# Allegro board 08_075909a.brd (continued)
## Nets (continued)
Pads without a net: MINIQ2 1 2 3 4 5 8; SHDNL_SEL 3; SW1 8 9; U2 6 9; U3 1 2; U4 3 4 5 6 9 10 11 12; U5 2

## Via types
v1: diameter 0.508, hole 0.254, TOP to BOTTOM, 507 vias

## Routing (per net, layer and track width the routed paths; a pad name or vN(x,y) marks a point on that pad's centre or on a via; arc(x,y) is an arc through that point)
3.3V: length 34.9
  TOP w0.381: U2.1 117.93,57.03 117.93,59.16 ; MINIQ1.15 124.71,45.85 124.71,55.75 123.95,56.52 R132.1 117.93,59.16 ; 117.93,59.16 117.22,59.87 117.22,66.29 117.94,67.01 U4.1
5.0V: length 101.4
  TOP w0.635: R34.2 119.85,99.03 v1(120.78,99.03)
  BOTTOM w0.762: J8.1 96.27,167.89 102.34,161.82 123.42,161.82 125.86,159.38 125.86,114.43 120.78,109.35 v1(120.78,99.03) 120.75,99.03 119.17,97.45 R24.2
GND_POWER: length 695.9
  TOP w0.203: v1(66.93,113.28) 67.14,113.07 67.53,113.07 U1.14 ; v1(19.71,160.66) 19.71,161.66 C104.2 ; D3.2 22,160.78 v1(20.7,160.78) ; 58.75,118.54 58.75,118.61 ; U1.6 70.1,109.99 v1(70.1,109.74) ; v1(69.44,110.49) 69.44,110.74 70.33,111.64 U1.8 ; D34.3 v1(20.57,144.27) ; v1(71.12,108.71) 71.65,108.71 71.88,108.94 U1.2 ; D29.3 v1(105.41,145.8)
  TOP w0.254: v1(61.98,109.22) 61.98,109.54 61.7,109.81 61.7,109.83 U1.28
  TOP w0.381: C81.2 v1(77.85,135.64) ; Q1.6 68.88,133.01 v1(69.22,133.35) ; v1(64.52,134.75) 64.99,134.75 Q1.3 ; U4.7 v1(121.84,68.24) ; C77.2 v1(79.76,134.11) ; U2.7 121.84,55.45 v1(122.17,55.12) ; 50,135.05 v1(48.9,136.15)
  TOP w0.508: v1(60.33,164.21) 60.31,164.22 GPIO_AUX2.2 ; J7.1 57.5,10.57 57.91,10.16 v1(60.2,10.16) ; v1(53.34,113.79) C14.2 ; C105.2 53.59,163.18 v1(53.59,162.18) ; C9.2 58.75,118.54 ; 71.34,116.83 71.32,116.83 C78.2 ; 71.34,116.83 71.81,117.3 v1(71.81,117.7) ; 71.34,116.83 71.07,116.56 70.97,116.56 ; C108.2 63.78,163.28 63.78,162.71 63.75,162.69 v1(63.75,162.31) ; 13.86,150.01 C102.1 14.06,150.01 ; J5.23 J5.24 ; v1(80.9,164.08) 80.89,164.1 GPIO_AUX0.2 ; v1(56.25,116.97) C11.2 ; v1(31.18,148.59) D28.A ; v1(41.03,165.97) 40.33,165.97 GPIO_AUX4.2 ; R152.2 v1(30.35,151.13) ; R155.2 v1(104.39,142.75) ; v1(75.44,10.16) 73.41,10.16 72.03,8.78 J7.GND1 ; v1(39.5,162.22) 39.5,161.77 D4.2 ; 14.06,138.65 C101.2 13.86,138.65 ; GPIO_AUX1.2 70.52,164.25 v1(70.48,164.21) ; R161.2 v1(104.39,148.84) ; R10.1 98.01,116.87 v1(97.65,117.24) ; C10.2 v1(57.27,117.99) ; J7.GND2 54.97,9.8 54.61,10.16 v1(52.32,10.16) ; GPIO_AUX3.2 50.13,164.25 v1(50.16,164.21) ; 58.75,118.61 v1(58.32,119.04) ; D7.2 v1(59.18,158.24) ; C109.2 41.77,163.58 v1(42.8,163.58) ; v1(73.91,162.18) 73.91,163.28 C107.2 ; v1(54.1,114.88) 54.28,114.88 C13.2 55.1,114.07 ; C12.2 55.31,115.89 v1(55.12,115.89) ; D6.2 v1(69.34,158.24) ; 27.3,161.74 R31.2 ; v1(61.72,122.17) C83.2 ; C106.2 84.35,163.21 v1(84.35,161.67) ; R150.2 v1(30.35,137.41) ; GPIO_AUX5.2 20.01,165.97 v1(20.71,165.97) ; 44.61,136.85 43.55,137.91 43.55,137.93 v1(43.05,138.43) ; D5.2 v1(79.76,158.24) ; 60.18,119.15 C8.2 59.31,120.02 v1(59.26,120.02) ; v1(31.18,139.95) D31.A ; D32.3 25.83,127.25 v1(24.39,127.25) ; C80.2 v1(60.45,120.9) ; D33.3 v1(111,127.76) ; D8.2 v1(49.02,158.24) ; R168.2 v1(18.03,123.19) ; R169.2 v1(18.29,131.57)
  TOP w0.635: ALARM_OUT_LP.GND1 4.22,104.89 ; 4.22,104.89 v1(5.83,104.89) ; 4.22,104.89 ALARM_OUT_LP.GND2 ; GPIO_AUX0.GND1 77.18,171.02 v1(80.01,171.02) 83.09,171.02 GPIO_AUX0.GND2 ; v1(77.47,102.87) 78.86,101.48 78.86,101.46 C18.2 v1(80.26,100.08) ; GPIO_AUX5.GND2 21.88,171.07 v1(19.05,171.07) 15.97,171.07 GPIO_AUX5.GND1 ; RXLP_CONN.GND2 v1(2.8,132.59) ; C21.2 91.98,94.1 v1(92.91,93.17) ; v1(76.68,113.28) 75.74,112.34 C3.2 ; TXLP_CONN.GND1 v1(2.8,139.19) ; v1(123.8,104.9) 123.8,102.66 ALARM_IN_UP.GND2 ; TXUP_CONN.GND1 123.82,131.64 v1(123.82,133.22) ; v1(94.61,121.28) R134.2 ; v1(88.14,160.02) C17.2 88.14,161.43 ; 90.4,162.8 C16.2 ; 90.4,162.8 90.4,164.78 R139.2 ; 90.4,162.8 v1(90.4,161.57) ; C82.2 69.36,118.16 v1(69.19,118.16) ; GPIO_AUX3.GND1 46.42,171.04 v1(49.53,171.04) 52.33,171.04 GPIO_AUX3.GND2 ; v1(108.08,109.19) 107.21,109.19 C87.2 ; R110.2 108.05,114.96 v1(108.2,114.81) ; v1(27.3,160.15) 27.3,161.74 ; v1(9.14,97.79) C93.2 10.64,97.79 10.64,99.09 10.41,99.31 D9.A ; RXLP_CONN.GND1 v1(2.8,122.43) ; C5.2 v1(73.38,116.05) ; GPIO_AUX2.GND1 56.61,171.07 v1(59.44,171.07) 62.52,171.07 GPIO_AUX2.GND2 ; U5.4 102.06,106.91 102.97,107.82 v1(104.27,107.82) ; R112.2 11.17,110.02 D10.A 10.22,109.97 v1(9.41,109.97) ; v1(93.66,123.7) D30.A ; R30.1 v1(40.89,123.7) ; C4.2 v1(75.18,114.3) ; 14.06,138.65 v1(15.01,138.65) ; GPIO_AUX1.GND2 72.73,171.07 v1(70.1,171.07) 66.82,171.07 GPIO_AUX1.GND1 ; C15.2 v1(77.98,112.01) ; RXUP_CONN.GND1 124.59,149.54 v1(124.59,150.88) ; TXUP_CONN.GND2 123.82,124.14 v1(123.82,122.94) ; v1(93.66,132.08) D26.A ; v1(123.8,106.05) 123.8,108.57 ALARM_IN_UP.GND1 ; R147.2 95.62,134.54 v1(94.23,134.54) ; CURRENTSENSE.GND2 32.17,171.19 v1(29.21,171.19) 26.25,171.19 CURRENTSENSE.GND1 ; GPIO_AUX4.GND2 42.2,171.07 v1(39.37,171.07) 36.29,171.07 GPIO_AUX4.GND1 ; v1(124.59,140.91) 124.59,142.05 RXUP_CONN.GND2 ; C100.2 v1(114.71,13.26) ; 14.06,150.01 v1(15.06,150.01) ; TXLP_CONN.GND2 v1(2.8,149.61)
  L2_GND w0.381: v1(69.22,133.35) 69.34,133.35 ; v1(69.22,133.35) 69.09,133.35 ; v1(69.22,133.35) 69.22,133.48 ; v1(69.22,133.35) 69.22,133.22 ; 91.82,140.21 v1(91.95,140.21) ; v1(91.95,140.21) 92.08,140.21 ; v1(91.95,140.21) 91.95,140.34 ; v1(91.95,140.21) 91.95,140.08 ; v1(108.08,109.19) 108.2,109.19 ; v1(108.08,109.19) 108.08,109.07 ; v1(108.08,109.19) 107.95,109.19 ; v1(108.08,109.19) 108.08,109.32 ; v1(70.1,109.74) 70.23,109.74 ; v1(70.1,109.74) 70.1,109.87 ; v1(70.1,109.74) 69.98,109.74 ; v1(70.1,109.74) 70.1,109.61 ; 94.61,121.16 v1(94.61,121.28) ; v1(94.61,121.28) 94.74,121.28 ; v1(94.61,121.28) 94.49,121.28 ; v1(94.61,121.28) 94.61,121.41 ; 79.63,134.11 v1(79.76,134.11) ; v1(79.76,134.11) 79.88,134.11 ; v1(79.76,134.11) 79.76,133.98 ; v1(79.76,134.11) 79.76,134.24 ; 69.31,110.49 v1(69.44,110.49) ; v1(69.44,110.49) 69.44,110.62 ; v1(69.44,110.49) 69.57,110.49 ; v1(69.44,110.49) 69.44,110.36 ; 77.98,111.89 v1(77.98,112.01) ; v1(77.98,112.01) 77.85,112.01 ; v1(77.98,112.01) 77.98,112.14 ; v1(77.98,112.01) 78.11,112.01 ; v1(76.25,111.53) 76.38,111.53 ; v1(76.25,111.53) 76.12,111.53 ; v1(76.25,111.53) 76.25,111.66 ; v1(76.25,111.53) 76.25,111.4 ; 93.18,113.22 J1.2 ; J1.2 94.89,113.22 ; J1.2 93.18,111.51 ; J1.2 94.89,111.51 ; J1.8 84.12,122.28 ; J1.8 82.41,123.99 ; J1.8 82.41,122.28 ; J1.8 84.12,123.99 ; J5.23 33.53,152.34 ; J5.23 32.32,151.13 ; J5.23 33.53,149.92 ; J5.23 34.74,151.13 ; 91.95,102.53 v1(91.95,102.66) ; v1(91.95,102.66) 92.08,102.66 ; v1(91.95,102.66) 91.82,102.66 ; v1(91.95,102.66) 91.95,102.78 ; v1(71.81,117.7) 71.93,117.7 ; v1(71.81,117.7) 71.81,117.58 ; v1(71.81,117.7) 71.68,117.7 ; v1(71.81,117.7) 71.81,117.83 ; v1(111,127.76) 111,127.89 ; v1(111,127.76) 111,127.63 ; v1(111,127.76) 111.13,127.76 ; v1(111,127.76) 110.87,127.76 ; 45.02,148.59 J5.14 ; J5.14 47.44,148.59 ; J5.14 46.23,147.38 ; J5.14 46.23,149.8 ; 84.84,106.93 v1(84.96,106.93) ; v1(84.96,106.93) 84.96,106.81 ; v1(84.96,106.93) 84.96,107.06 ; v1(84.96,106.93) 85.09,106.93 ; 104.14,107.82 v1(104.27,107.82) ; v1(104.27,107.82) 104.27,107.95 ; v1(104.27,107.82) 104.27,107.7 ; v1(104.27,107.82) 104.39,107.82 ; 76.56,113.28 v1(76.68,113.28) ; v1(76.68,113.28) 76.81,113.28 ; v1(76.68,113.28) 76.68,113.41 ; v1(76.68,113.28) 76.68,113.16 ; 38.61,149.92 J5.19 ; J5.19 38.61,152.34 ; J5.19 39.82,151.13 ; J5.19 37.4,151.13 ; J5.8 53.85,149.8 ; J5.8 55.06,148.59 ; J5.8 52.64,148.59 ; J5.8 53.85,147.38 ; 75.06,114.3 v1(75.18,114.3) ; v1(75.18,114.3) 75.18,114.43 ; v1(75.18,114.3) 75.18,114.17 ; v1(75.18,114.3) 75.31,114.3 ; J5.1 61.47,152.34 ; J5.1 61.47,149.92 ; J5.1 62.68,151.13 ; J5.1 60.26,151.13 ; 104.65,133.73 v1(104.65,133.86) ; v1(104.65,133.86) 104.78,133.86 ; v1(104.65,133.86) 104.65,133.99 ; v1(104.65,133.86) 104.52,133.86 ; 94.11,134.54 v1(94.23,134.54) ; v1(94.23,134.54) 94.36,134.54 ; v1(94.23,134.54) 94.23,134.67 ; v1(94.23,134.54) 94.23,134.41 ; 88.67,129.46 v1(88.8,129.46) ; v1(88.8,129.46) 88.93,129.46 ; v1(88.8,129.46) 88.8,129.59 ; v1(88.8,129.46) 88.8,129.34 ; 5.08,20.95 B0P-.1 ; B0P-.1 5.08,23.24 ; B0P-.1 6.22,22.1 ; B0P-.1 3.94,22.1 ; v1(111.76,120.9) 111.89,120.9 ; v1(111.76,120.9) 111.76,121.03 ; v1(111.76,120.9) 111.76,120.78 ; v1(111.76,120.9) 111.63,120.9 ; v1(100.58,96.77) 100.58,96.9 ; v1(100.58,96.77) 100.46,96.77 ; v1(100.58,96.77) 100.71,96.77 ; v1(100.58,96.77) 100.58,96.65 ; v1(73.38,116.05) 73.38,116.18 ; v1(73.38,116.05) 73.38,115.93 ; v1(73.38,116.05) 73.51,116.05 ; v1(73.38,116.05) 73.25,116.05 ; v1(97.65,117.24) 97.77,117.24 ; v1(97.65,117.24) 97.65,117.11 ; v1(97.65,117.24) 97.52,117.24 ; v1(97.65,117.24) 97.65,117.37 ; v1(71.12,108.71) 71.12,108.84 ; v1(71.12,108.71) 71.12,108.58 ; v1(71.12,108.71) 70.99,108.71 ; v1(71.12,108.71) 71.25,108.71 ; 77.47,102.74 v1(77.47,102.87) ; v1(77.47,102.87) 77.6,102.87 ; v1(77.47,102.87) 77.47,103 ; v1(77.47,102.87) 77.34,102.87 ; 93.53,132.08 v1(93.66,132.08) ; v1(93.66,132.08) 93.66,131.95 ; v1(93.66,132.08) 93.66,132.21 ; v1(93.66,132.08) 93.79,132.08 ; J1.6 87.71,120.4 ; J1.6 87.71,118.69 ; J1.6 86,118.69 ; J1.6 86,120.4 ; 64.52,134.62 v1(64.52,134.75) ; v1(64.52,134.75) 64.39,134.75 ; v1(64.52,134.75) 64.52,134.87 ; v1(64.52,134.75) 64.64,134.75 ; 38.61,147.38 J5.20 ; J5.20 37.4,148.59 ; J5.20 39.82,148.59 ; J5.20 38.61,149.8 ; J5.13 47.44,151.13 ; J5.13 46.23,152.34 ; J5.13 46.23,149.92 ; J5.13 45.02,151.13 ; v1(66.93,113.28) 67.06,113.28 ; v1(66.93,113.28) 66.93,113.41 ; v1(66.93,113.28) 66.8,113.28 ; v1(66.93,113.28) 66.93,113.16 ; v1(78.36,125.09) 78.36,125.22 ; v1(78.36,125.09) 78.23,125.09 ; v1(78.36,125.09) 78.49,125.09 ; v1(78.36,125.09) 78.36,124.97 ; v1(77.85,135.64) 77.85,135.76 ; v1(77.85,135.64) 77.98,135.64 ; v1(77.85,135.64) 77.85,135.51 ; v1(77.85,135.64) 77.72,135.64 ; 91.95,126.92 v1(91.95,127.05) ; v1(91.95,127.05) 91.82,127.05 ; v1(91.95,127.05) 91.95,127.18 ; v1(91.95,127.05) 92.08,127.05 ; J1.14 73.34,133.06 ; J1.14 71.63,133.06 ; J1.14 73.34,134.77 ; J1.14 71.63,134.77 ; J5.24 33.53,149.8 ; J5.24 34.74,148.59 ; J5.24 33.53,147.38 ; J5.24 32.32,148.59 ; 92.91,93.04 v1(92.91,93.17) ; v1(92.91,93.17) 93.04,93.17 ; v1(92.91,93.17) 92.79,93.17 ; v1(92.91,93.17) 92.91,93.29 ; 105.66,43.37 MINIQ1.1 ; MINIQ1.1 105.66,45.78 ; MINIQ1.1 104.46,44.58 ; MINIQ1.1 106.87,44.58 ; v1(64.52,109.22) 64.52,109.35 ; v1(64.52,109.22) 64.52,109.09 ; v1(64.52,109.22) 64.39,109.22 ; v1(64.52,109.22) 64.64,109.22 ; 79.25,120.65 v1(79.38,120.65) ; v1(79.38,120.65) 79.5,120.65 ; v1(79.38,120.65) 79.38,120.78 ; v1(79.38,120.65) 79.38,120.52 ; v1(69.19,118.16) 69.19,118.29 ; v1(69.19,118.16) 69.06,118.16 ; v1(69.19,118.16) 69.19,118.03 ; v1(69.19,118.16) 69.32,118.16 ; 108.2,114.68 v1(108.2,114.81) ; v1(108.2,114.81) 108.33,114.81 ; v1(108.2,114.81) 108.2,114.94 ; v1(108.2,114.81) 108.08,114.81 ; v1(111.51,137.41) 111.63,137.41 ; v1(111.51,137.41) 111.51,137.54 ; v1(111.51,137.41) 111.51,137.29 ; v1(111.51,137.41) 111.38,137.41 ; J2.12 44.06,116.88 ; J2.12 44.06,118.59 ; J2.12 42.36,116.88 ; J2.12 42.36,118.59 ; 91.19,168.72 J8.3 ; J8.3 92.39,169.93 ; J8.3 91.19,171.13 ; J8.3 89.98,169.93 ; 93.53,123.7 v1(93.66,123.7) ; v1(93.66,123.7) 93.66,123.83 ; v1(93.66,123.7) 93.79,123.7 ; v1(93.66,123.7) 93.66,123.57 ; 52.64,151.13 J5.7 ; J5.7 53.85,152.34 ; J5.7 53.85,149.92 ; J5.7 55.06,151.13 ; v1(80.26,100.08) 80.39,100.08 ; v1(80.26,100.08) 80.26,100.2 ; v1(80.26,100.08) 80.26,99.95 ; v1(80.26,100.08) 80.14,100.08 ; MINIQ2.6 119.5,94.89 ; MINIQ2.6 118.29,93.69 ; MINIQ2.6 117.08,94.89 ; MINIQ2.6 118.29,96.1 ; 60.26,148.59 J5.2 ; J5.2 61.47,149.8 ; J5.2 62.68,148.59 ; J5.2 61.47,147.38 ; 65.99,107.62 v1(66.12,107.62) ; v1(66.12,107.62) 66.24,107.62 ; v1(66.12,107.62) 66.12,107.49 ; v1(66.12,107.62) 66.12,107.75 ; v1(66.55,102.11) 66.68,102.11 ; v1(66.55,102.11) 66.42,102.11 ; v1(66.55,102.11) 66.55,101.98 ; v1(66.55,102.11) 66.55,102.24
  L3_GND w0.381: 91.19,168.72 J8.3 ; J8.3 92.39,169.93 ; J8.3 91.19,171.13 ; J8.3 89.98,169.93 ; 32.32,151.13 J5.23 ; J5.23 33.53,149.92 ; J5.23 34.74,151.13 ; J5.23 33.53,152.34 ; J1.6 87.71,120.4 ; J1.6 86,120.4 ; J1.6 86,118.69 ; J1.6 87.71,118.69 ; J5.1 62.68,151.13 ; J5.1 61.47,152.34 ; J5.1 61.47,149.92 ; J5.1 60.26,151.13 ; 33.53,147.38 J5.24 ; J5.24 34.74,148.59 ; J5.24 33.53,149.8 ; J5.24 32.32,148.59 ; J1.2 94.89,113.22 ; J1.2 94.89,111.51 ; J1.2 93.18,111.51 ; J1.2 93.18,113.22 ; 45.02,148.59 J5.14 ; J5.14 46.23,147.38 ; J5.14 46.23,149.8 ; J5.14 47.44,148.59 ; J5.20 39.82,148.59 ; J5.20 38.61,147.38 ; J5.20 38.61,149.8 ; J5.20 37.4,148.59 ; 46.23,149.92 J5.13 ; J5.13 47.44,151.13 ; J5.13 46.23,152.34 ; J5.13 45.02,151.13 ; 117.08,94.89 MINIQ2.6 ; MINIQ2.6 119.5,94.89 ; MINIQ2.6 118.29,96.1 ; MINIQ2.6 118.29,93.69 ; MINIQ1.1 105.66,45.78 ; MINIQ1.1 105.66,43.37 ; MINIQ1.1 106.87,44.58 ; MINIQ1.1 104.46,44.58 ; 82.41,123.99 J1.8 ; J1.8 84.12,122.28 ; J1.8 82.41,122.28 ; J1.8 84.12,123.99 ; J1.14 73.34,133.06 ; J1.14 73.34,134.77 ; J1.14 71.63,134.77 ; J1.14 71.63,133.06 ; J5.2 62.68,148.59 ; J5.2 61.47,147.38 ; J5.2 60.26,148.59 ; J5.2 61.47,149.8 ; 52.64,148.59 J5.8 ; J5.8 55.06,148.59 ; J5.8 53.85,149.8 ; J5.8 53.85,147.38 ; J5.7 55.06,151.13 ; J5.7 53.85,152.34 ; J5.7 53.85,149.92 ; J5.7 52.64,151.13 ; B0P-.1 5.08,23.24 ; B0P-.1 6.22,22.1 ; B0P-.1 5.08,20.95 ; B0P-.1 3.94,22.1 ; J5.19 39.82,151.13 ; J5.19 38.61,152.34 ; J5.19 37.4,151.13 ; J5.19 38.61,149.92 ; 42.36,116.88 J2.12 ; J2.12 44.06,116.88 ; J2.12 44.06,118.59 ; J2.12 42.36,118.59
  L3_GND w0.635: PACK-.1 2.55,12.9 ; PACK-.1 5.07,12.9 ; PACK-.1 2.55,18.59 ; PACK-.1 5.07,18.59 ; B0P-.1 3.92,20.94 ; B0P-.1 3.92,23.25 ; B0P-.1 6.24,20.94 ; B0P-.1 6.24,23.25
  BOTTOM w0.254: 75.11,110.92 C2.2
  BOTTOM w0.305: v1(105.66,42.8) MINIQ1.1 ; D25.2 v1(98.17,46.1)
  BOTTOM w0.381: 74.57,111.38 74.95,111 C2.2 75.26,110.77 75.67,110.36 ; 46.76,8.81 46.76,8.82 C43.1 46.76,11.45 46.76,11.46 ; 45.02,151.13 J5.13 ; J5.13 47.44,151.13 ; J5.13 46.23,152.34 ; 115.82,52.45 D21.2 v1(115.82,51.31) ; 37.4,148.59 J5.20 38.61,147.38 ; 91.95,102.53 v1(91.95,102.66) ; v1(91.95,102.66) 92.08,102.66 ; v1(91.95,102.66) 91.82,102.66 ; v1(91.95,102.66) 91.95,102.78 ; v1(110.74,51.31) D23.2 110.74,52.45 ; 72.13,114.79 72.41,114.5 C76.2 72.62,114.2 73,113.82 ; J2.12 44.06,118.59 ; J2.12 44.06,116.88 ; J2.12 42.36,116.88 ; J2.12 42.36,118.59 ; 120.9,52.45 D19.2 v1(120.9,51.31) ; 54.38,8.81 54.38,8.82 C42.1 54.38,11.45 54.38,11.46 ; J1.6 87.71,120.4 ; J1.6 86,118.69 ; J1.6 86,120.4 ; J1.6 87.71,118.69 ; MINIQ2.6 119.5,94.89 ; MINIQ2.6 118.29,96.1 ; MINIQ2.6 118.29,93.69 ; 31.52,11.46 31.52,11.45 C45.1 31.52,8.82 31.52,8.81 ; J5.2 62.68,148.59 ; J5.2 60.26,148.59 ; J5.2 61.47,147.38 ; 45.02,148.59 J5.14 46.23,147.38 ; 62,11.46 62,11.45 C41.1 62,8.82 62,8.81 ; 84.96,106.81 v1(84.96,106.93) ; v1(84.96,106.93) 84.96,107.06 ; v1(84.96,106.93) 85.09,106.93 ; v1(84.96,106.93) 84.84,106.93 ; 23.9,8.81 23.9,8.82 C46.1 23.9,11.45 23.9,11.46 ; B0P-.1 6.22,22.1 ; B0P-.1 5.08,23.24 ; B0P-.1 3.94,22.1 ; B0P-.1 5.08,20.95 ; Q2.6 78.1,124.83 v1(78.36,125.09) ; 108.2,52.45 D24.2 v1(108.2,51.31) ; 32.32,151.13 J5.23 ; J5.23 34.74,151.13 ; J5.23 33.53,152.34 ; J5.23 33.53,149.92 ; J5.19 39.82,151.13 ; J5.19 38.61,152.34 ; J5.19 37.4,151.13 ; 71.63,134.77 J1.14 ; J1.14 71.63,133.06 ; J1.14 73.34,134.77 ; 32.23,115.95 31.6,115.32 C84.2 31.16,114.96 30.45,114.25 ; 84.86,11.46 84.86,11.45 C38.1 84.86,8.82 84.86,8.81 ; 35.41,116.56 34.74,115.89 C85.2 34.73,115.83 34.16,115.27 ; R12.1 89.65,128.69 90.35,127.99 ; R12.1 89.54,128.69 88.95,128.09 ; R12.1 89.57,128.69 v1(88.8,129.46) ; 39.14,8.81 39.14,8.82 C44.1 39.14,11.45 39.14,11.46 ; v1(113.28,51.31) D22.2 113.28,52.45 ; J5.24 33.53,149.8 ; J5.24 34.74,148.59 ; J5.24 33.53,147.38 ; J5.24 32.32,148.59 ; J5.7 55.06,151.13 ; J5.7 52.64,151.13 ; J5.7 53.85,152.34 ; 65.6,110.46 65.12,109.98 R28.2 65.14,109.89 65.74,109.3 ; 107.72,8.81 107.72,8.82 C35.1 107.72,11.45 107.72,11.46 ; C19.2 87.1,105.08 ; C19.2 84.66,102.64 ; C19.2 85.05,104.68 ; 115.34,11.46 115.34,11.45 C34.1 115.34,8.82 115.34,8.81 ; v1(118.36,51.31) D20.2 118.36,52.45 ; 82.41,123.99 J1.8 ; J1.8 84.12,123.99 ; J1.8 82.41,122.28 ; J1.8 84.12,122.28 ; 91.19,168.72 J8.3 ; J8.3 92.39,169.93 ; J8.3 89.98,169.93 ; J8.3 91.19,171.13 ; J1.2 94.89,111.51 ; J1.2 93.18,113.22 ; J1.2 93.18,111.51 ; J1.2 94.89,113.22 ; v1(79.38,120.65) 79.33,120.69 79.33,121.2 Q2.3 ; 92.48,8.81 92.48,8.82 C37.1 92.48,11.45 92.48,11.46 ; J5.1 62.68,151.13 ; J5.1 61.47,152.34 ; J5.1 60.26,151.13 ; 53.85,147.38 J5.8 52.64,148.59 ; MINIQ1.1 106.87,44.58 ; MINIQ1.1 105.66,45.78 ; MINIQ1.1 104.46,44.58 ; 63.83,115.21 63.24,114.62 C7.2 63.18,114.56 62.61,114 ; 123.44,52.45 D18.2 v1(123.44,51.31) ; 69.62,8.81 69.62,8.82 C40.1 69.62,11.45 69.62,11.46 ; 77.24,8.81 77.24,8.82 C39.1 77.24,11.45 77.24,11.46 ; 16.28,11.46 16.28,11.45 C47.1 16.28,8.82 16.28,8.81 ; 100.1,11.46 100.1,11.45 C36.1 100.1,8.82 100.1,8.81
  BOTTOM w0.508: 57.73,74.07 58.29,73.51 C26.2 ; 46.33,84.56 46.96,83.93 C29.2 ; v1(73.38,116.05) 73.15,115.82 73.15,114.94 C76.2 ; C26.2 v1(57.4,72.14) ; C26.2 58.78,73.12 59.56,72.34 ; 54.2,77.48 54.62,77.07 C27.2 ; v1(88.87,88.22) 89.56,88.91 C20.2 90.16,89.51 90.75,90.11 90.75,90.12 ; C30.2 44.05,87.14 44.73,86.46 ; C30.2 43.44,87.48 43.03,87.9 ; C30.2 v1(42.67,86.11) ; v1(62.87,115.7) 63.18,115.38 C7.2 ; C33.2 v1(32.09,97.11) ; C33.2 32.79,98.4 32.26,98.93 ; C33.2 33.38,97.81 33.99,97.21 ; C32.2 36.94,94.3 37.49,93.75 ; C32.2 36.32,94.85 35.79,95.38 ; C32.2 v1(35.56,93.47) ; 51.79,79.1 51.16,79.73 C28.2 ; C27.2 v1(53.84,75.69) ; C27.2 55.22,76.6 55.98,75.84 ; 67.29,109.32 C79.2 66.12,108.15 v1(66.12,107.62) ; C29.2 v1(46.23,82.55) ; C29.2 47.6,83.51 48.29,82.83 ; C31.2 40.49,90.37 41,89.87 ; C31.2 39.85,91.04 39.32,91.57 ; C31.2 v1(39.12,89.66) ; v1(76.25,111.53) 76.23,111.51 75.69,111.51 75.11,110.92 ; D14.2 v1(113.28,37.21) ; 81.64,80.92 82.19,81.48 C23.2 82.78,82.15 v1(83.47,82.84) ; J5.19 J5.20 ; 85.33,84.68 85.75,85.1 C22.2 86.34,85.7 v1(87.06,86.42) ; v1(79.92,79.28) 79.24,78.59 C24.2 78.63,78.07 77.95,77.39 ; C28.2 50.55,80.12 50.14,80.53 ; C28.2 v1(49.78,78.74) ; D15.2 v1(110.74,37.21) ; J5.7 J5.8 ; D16.2 v1(108.2,37.21) ; D11.2 v1(120.9,37.85) ; D13.2 v1(115.82,37.59) ; v1(76.36,75.73) 75.67,75.04 C25.2 75.08,74.43 74.66,74.01 ; D12.2 v1(118.36,37.59) ; R28.2 65.12,109.82 v1(64.52,109.22)
  BOTTOM w0.635: v1(105.66,10.16) C35.1 ; v1(82.8,10.16) C38.1 ; v1(29.72,10.16) C45.1 ; v1(52.32,10.16) C42.1 ; v1(98.04,10.16) C36.1 ; v1(60.2,10.16) C41.1 ; v1(44.7,10.16) C43.1 ; v1(75.44,10.16) C39.1 ; v1(21.59,10.16) C46.1 ; v1(67.56,10.16) C40.1 ; J5.13 J5.14 ; v1(37.34,10.16) C44.1 ; v1(14.22,10.16) C47.1 ; v1(90.42,10.16) C37.1 ; J5.1 J5.2 ; v1(113.28,10.16) C34.1
  BOTTOM w0.889: v1(30.23,116.33) C84.2 ; C85.2 v1(33.53,117.09)
  vias: v1(1.02,1.02) v1(2.92,155.96) v1(3.05,171.96) v1(3.05,95.63) v1(3.05,83.06) v1(3.05,70.36) v1(3.05,57.66) v1(3.05,44.96) v1(3.05,32.26) v1(3.05,19.56) v1(6.22,161.93) v1(6.22,136.65) v1(9.91,63.5) v1(10.16,19.81) v1(13.97,19.81) v1(14.22,64.52) v1(14.22,60.45) v1(14.99,93.98) v1(14.99,68.83) v1(15.75,152.91) v1(15.75,140.21) v1(15.75,127.51) v1(15.75,114.81) v1(15.75,102.11) v1(15.75,76.71) v1(15.75,51.31) v1(15.75,38.61) v1(15.75,13.21) v1(16.26,26.04) v1(17.78,19.81) v1(18.29,62.99) v1(20.83,64.52) v1(20.83,60.45) v1(21.59,91.69) v1(21.59,75.18) v1(21.59,20.83) v1(22.1,54.1) v1(23.62,68.58) v1(24.89,62.99) v1(25.15,19.56) v1(25.65,24.89) v1(27.94,64.52) v1(27.94,60.45) v1(28.45,133.86) v1(28.45,121.16) v1(28.45,108.46) v1(28.45,95.76) v1(28.45,83.06) v1(28.45,70.36) v1(28.42,56.52) v1(28.45,44.96) v1(28.45,32.26) v1(28.45,6.86) v1(29.08,19.56) v1(29.34,146.94) v1(31.75,63.25) v1(33.02,103.89) v1(33.02,19.56) v1(33.27,51.31) v1(33.53,156.72) v1(33.53,146.05) v1(34.8,64.52) v1(34.8,60.45) v1(36.58,29.72) v1(36.83,19.56) v1(37.08,33.27) v1(37.72,115.57) v1(37.85,132.59) v1(37.85,70.36) v1(37.85,27.69) v1(38.35,156.46) v1(38.35,58.17) v1(38.99,64.26) v1(40.64,19.56) v1(41.15,141.35) v1(41.15,127.38) v1(41.15,38.61) v1(41.15,25.91) v1(41.15,13.21) v1(41.27,52.02) v1(41.4,64.52) v1(41.66,101.98) v1(41.66,60.45) v1(41.66,34.29) v1(42.42,77.22) v1(43.18,32.77) v1(43.43,54.61) v1(43.69,68.83) v1(44.2,156.46) v1(44.45,19.81) v1(44.7,129.79) v1(44.96,149.61) v1(45.72,143) v1(45.72,106.68) v1(45.72,36.58) v1(45.97,62.99) v1(47.5,118.75) v1(47.5,55.88) v1(47.5,49.28) v1(48.01,19.56) v1(49.02,129.03) v1(49.02,64.52) v1(49.28,120.65) v1(49.78,28.45) v1(50.04,99.31) v1(50.04,70.1) v1(50.55,55.63) v1(50.8,47.5) v1(50.8,42.67) v1(51.44,122.56) v1(51.56,129.54) v1(52.07,142.75) v1(52.07,19.81) v1(52.58,149.86) v1(53.09,124.21) v1(53.09,64.01) v1(53.09,50.04) v1(53.21,58.67) v1(53.34,35.81) v1(53.72,83.82) v1(53.68,44.78) v1(53.85,108.46) v1(53.85,95.76) v1(53.85,70.36) v1(54.36,19.56) v1(54.48,32.26) v1(54.74,125.98) v1(55.63,156.46) v1(55.63,42.42) v1(55.63,35.81) v1(55.88,47.24) v1(55.88,19.56) v1(56.13,64.52) v1(57.02,127.89) v1(57.91,152.4) v1(58.42,49.78) v1(58.42,41.91) v1(59.69,58.42) v1(59.69,19.56) v1(59.94,35.05) v1(60.2,64.01) v1(60.71,49.78) v1(60.71,41.91) v1(62.23,56.39) v1(62.48,33.27) v1(63.25,70.1) v1(63.25,64.52) v1(63.25,49.78) v1(63.25,41.91) v1(63.25,19.56) v1(66.42,39.12) v1(66.55,152.91) v1(66.55,89.41) v1(66.55,76.71) v1(66.55,51.31) v1(66.67,146.05) v1(66.8,58.17) v1(67.07,64.78) v1(67.31,56.13) v1(67.31,26.67) v1(67.69,146.69) v1(67.82,1.02) v1(68.58,44.2) v1(68.83,50.29) v1(69.98,146.43) v1(70.1,64.52) v1(71.12,43.43) v1(71.12,20.83) v1(71.37,51.05) v1(71.63,71.63) v1(73.66,49.53) v1(73.66,40.13) v1(73.66,35.05) v1(73.91,64.77) v1(73.91,57.15) v1(74.93,20.07) v1(75.18,28.96) v1(76.2,50.04) v1(76.2,43.18) v1(77.72,64.52) v1(77.72,28.96) v1(77.85,32.26) v1(78.11,56.64) v1(78.74,49.53) v1(78.87,44.83) v1(79.25,146.43) v1(79.25,83.06) v1(79.25,70.36) v1(79.25,19.56) v1(79.25,6.86) v1(79.5,35.81) v1(81.28,58.17) v1(81.28,49.78) v1(81.28,42.67) v1(81.28,31.5) v1(81.53,63.25) v1(81.79,36.07) v1(82.3,20.07) v1(82.8,25.4) v1(83.82,47.24) v1(84.33,36.07) v1(84.84,72.64) v1(85.09,64.52) v1(85.09,55.37) v1(85.34,28.45) v1(85.85,19.81) v1(86.87,36.07) v1(87.12,2.79) v1(88.01,38.43) v1(88.14,28.45) v1(88.65,62.99) v1(91.19,68.58) v1(91.95,152.91) v1(91.95,72.39) v1(91.95,51.31) v1(91.95,38.61) v1(91.95,13.21) v1(92.04,166.18) v1(92.08,77.22) v1(92.2,64.52) v1(92.33,26.16) v1(92.96,55.12) v1(93.73,19.81) v1(93.98,45.97) v1(94.23,30.99) v1(95.5,62.99) v1(97.03,33.53) v1(97.79,68.58) v1(98.55,72.9) v1(99.06,53.59) v1(99.31,64.52) v1(99.31,60.45) v1(99.57,25.4) v1(101.35,19.81) v1(102.11,60.45) v1(103.63,64.52) v1(104.39,53.09) v1(104.65,171.96) v1(104.65,159.26) v1(104.65,146.56) v1(104.65,83.06) v1(104.57,69.77) v1(104.65,32.26) v1(104.65,27.18) v1(104.65,6.86) v1(104.9,91.19) v1(105.16,39.62) v1(105.28,19.68) v1(106.43,64.52) v1(106.43,60.45) v1(106.68,34.29) v1(106.68,14.73) v1(107.95,2.54) v1(108.97,20.07) v1(109.47,69.6) v1(109.73,88.65) v1(109.98,80.26) v1(110.24,62.74) v1(111.76,28.7) v1(112.78,20.57) v1(113.28,7.11) v1(113.54,64.52) v1(113.54,60.45) v1(113.79,89.15) v1(113.79,14.99) v1(114.55,55.88) v1(115.32,80.01) v1(115.39,76.71) v1(116.33,62.74) v1(116.59,20.32) v1(116.71,114.3) v1(117.35,165.61) v1(117.35,102.11) v1(117.35,38.61) v1(117.35,25.91) v1(117.35,6.86) v1(117.47,156.46) v1(118.36,89.41) v1(119.89,72.64) v1(120.4,67.82) v1(121.67,65.53) v1(121.67,32.77) v1(122.94,86.61) v1(124.46,10.92) v1(124.71,23.88) v1(124.97,2.29) v1(125.73,172.97) v1(125.73,161.04)
VDDL1: length 27.7
  TOP w0.254: 72.58,111.76 71.4,110.58 U1.5
  TOP w0.381: 72.58,111.76 73.29,112.47 C4.1 72.98,112.85 72.98,113.3 75.02,115.34 79.72,115.34 R11.2 79.84,115.34 86.24,115.34 J1.5 88.9,118 88.9,123.29 VDDL1.1
VDDL2/VDDL3: length 203.6
  TOP w0.203: R142.1 110.59,100.04 110.53,100.1
  TOP w0.305: v1(65.16,112.71) 65.16,112.72 64.13,113.75 U1.19 ; v1(68.47,111.62) 68.47,111.89 U1.11 70.29,113.71 71.04,113.71 C5.1
  TOP w0.381: v1(72.34,130.12) 71.17,131.29 v1(70.26,131.29) 70.1,131.44 69.22,131.44 Q1.5 ; Q1.2 65.79,134.87 65.79,135.84 v1(66.47,136.53) ; v1(105.05,124.21) R133.1 ; R146.1 v1(105.08,131.57)
  TOP w0.457: U2.14 117.94,65.36 119.51,66.93 v1(121.67,66.93) ; U4.14 117.94,77.81
  TOP w0.508: R26.2 58.8,137.36 58.8,134.47 J2.3 ; 117.94,77.81 119.25,79.12
  TOP w0.635: 119.25,79.12 123.7,79.12 125.76,81.18 v1(125.76,81.41) 125.76,95.35 124.21,96.9 117.37,96.9 116.27,98.01 R32.2 ; R32.2 116.27,100.04 115.45,100.86 v1(114.92,100.86) 111.44,100.86 110.68,100.1 ; R32.2 116.32,99.01 117.87,99.01 R34.1 ; R154.1 v1(21.62,148.34) ; v1(100.08,103.5) 106.02,103.5 107.95,101.57 R114.1 110.53,100.1 ; 110.68,100.1 R142.1 110.55,100.1 110.68,100.1 ; R151.1 v1(21.72,140.21)
  L3_GND w0.381: J1.11 78.73,127.67 ; J1.11 77.02,127.67 ; J1.11 77.02,129.38 ; 60.23,134.75 J2.3 60.23,133.04
  L3_GND w0.635: v1(125.76,81.41) 124.79,80.44 124.79,68.33 123.39,66.93 v1(121.67,66.93) ; v1(105.05,124.21) 105.05,131.55 v1(105.08,131.57) 100.41,131.57 96.24,135.74 85.08,135.74 82.8,133.46 VDDL2/3.1 82.72,133.38 J1.11 ; J2.3 58.91,134.37 44.37,134.37 39.83,138.91 28.83,138.91 27.53,140.21 v1(21.72,140.21)
  BOTTOM w0.381: v1(80.09,121.39) 80.06,121.39 Q2.2 ; v1(21.72,140.21) 21.62,140.31 v1(21.62,148.34) ; 77.64,123.81 76.56,124.89 v1(76.15,124.89)
  BOTTOM w0.457: C7.1 65.09,112.71 v1(65.16,112.71)
  vias: v1(66.55,114.81) v1(79.25,108.46)
ALERTIN: length 71.9
  TOP w0.203: J1.7 81.06,117.35 76.33,117.35 72.39,113.41 72.39,112.99 71.64,112.23 70.69,111.28
  TOP w0.635: R113.2 99.44,107.06 102.18,109.8 v1(104.6,109.8) 105.56,110.77 C87.1 R110.1
  L3_GND w0.635: J1.7 86.11,122.39 86.11,125.35 ALERTIN.1 86.87,129.82 OPTO_OUT.1
  BOTTOM w0.381: R12.2 88.88,131.78 OPTO_OUT.1
  BOTTOM w0.635: v1(104.6,109.8) 104.6,111.1 100.63,115.06 95.38,115.06 87.99,122.45 86.17,122.45 J1.7
ALERTOUT: length 52.3
  TOP w0.203: R136.2 61.47,107.7 61.95,108.18 67.16,108.18 v1(67.18,108.2)
  TOP w0.254: ALERTOUT.1 57.58,135.46 J2.4 59.84,129.84 59.84,120.5 62.1,118.24 62.1,115.07 63.06,114.11 63.07,114.11 U1.20 64.52,112.67 64.52,111.51 67.18,108.84 v1(67.18,108.2)
  BOTTOM w0.203: v1(67.18,108.2) 69.47,108.2 R141.1 70.31,107.36
AUXGND: length 27
  TOP w0.305: U1.25 62.01,111.63 62.99,110.65 v1(62.99,110.63)
  BOTTOM w0.203: v1(62.99,110.63) 61.45,110.63 54.1,117.98 53.74,117.98 J2.9 46.1,125.62 AUXGND.1
  BOTTOM w0.254: v1(62.99,110.63) 63.46,110.63 R28.1
BAT0: length 184.6
  TOP w0.508: J6.2 46.74,48.51 41.91,53.34 R83.1 ; v1(57.5,4.95) J7.2
  BOTTOM w0.508: BAT0.1 11.75,17.78 12.71,18.74 12.71,19.55 12.7,19.56 B1B0.1 12.7,24.64 18.29,30.23 32.51,30.23 39.88,37.59 SW2.16 49.53,38.61 J6.1 J6.2 24.13,48.51 15.62,57.02 R74.1 R54.1 R77.1 ; BAT0.1 8.57,17.78 7.61,18.74 7.61,20.31 7.62,20.32 B0P-.2 ; BAT0.1 10.16,10.16 15.37,4.95 v1(57.5,4.95)
BAT1: length 167
  TOP w0.508: BAT1.1 21.34,14.22 58.42,14.22 59,13.64 J7.3 ; R82.1 45.53,54.58 46.25,54.58 52.07,48.77 J6.4
  BOTTOM w0.508: R52.1 R73.1 R70.1 22.48,57.02 29.46,50.04 51.31,50.04 52.07,49.28 J6.4 J6.3 52.07,38.61 SW2.15 49.02,35.56 41.4,35.56 33.78,27.94 24.89,27.94 20.32,23.37 B2B1.1 20.32,20.32 20.33,20.31 20.33,18.74 19.37,17.78 BAT1.1 ; BAT1.1 17.78,15.24 19.49,13.53 19.49,10.37 C47.2 ; BAT1.1 16,17.78 15.24,18.54 B1B0.2
BAT2: length 151.2
  TOP w0.508: v1(58.42,6.1) 59,5.52 J7.4 ; J6.6 54.61,49.53 49.62,54.52 R81.1
  BOTTOM w0.508: B2B1.2 22.86,20.32 22.85,20.31 22.85,18.74 23.81,17.78 BAT2.1 ; R51.1 R69.1 R68.1 29.34,57.28 35.31,51.31 53.59,51.31 54.61,50.29 J6.6 J6.5 54.61,38.61 SW2.14 50.29,34.29 42.93,34.29 33.78,25.15 29.72,25.15 27.94,23.37 B3B2.1 27.94,20.84 27.95,20.83 27.95,18.74 26.99,17.78 BAT2.1 ; BAT2.1 25.4,14.99 27.11,13.27 27.11,10.37 C46.2 27.11,9.95 27.11,6.92 27.94,6.1 v1(58.42,6.1)
BAT3: length 133.2
  TOP w0.508: J6.8 57.15,49.28 53.09,53.34 R87.1 ; J7.5 60.5,14.43 59.94,14.99 38.99,14.99 36.2,17.78 BAT3.1
  BOTTOM w0.508: BAT3.1 34.37,17.78 35.56,18.97 B4B3.1 35.56,23.37 44.96,32.77 51.31,32.77 SW2.13 57.15,38.61 J6.7 J6.8 57.15,50.04 54.36,52.83 40.64,52.83 36.2,57.28 R67.1 R65.1 R50.1 ; BAT3.1 33.02,14.73 34.72,13.03 34.72,10.36 C45.2 ; BAT3.1 31.7,17.78 30.48,19 B3B2.2
BAT4: length 117.8
  TOP w0.508: R86.1 56.9,53.09 59.69,50.29 J6.10 ; v1(60.5,6.05) J7.6
  BOTTOM w0.508: B4B3.2 38.1,18.54 38.86,17.78 BAT4.1 ; v1(60.5,6.05) 60.5,6.3 59.69,7.11 57.4,7.11 56.59,7.93 43.23,7.93 42.14,9.02 C44.2 42.37,10.39 42.37,13.89 40.64,15.62 BAT4.1 ; 43.31,66.55 43.31,57.02 45.97,54.36 55.12,54.36 59.69,49.78 J6.10 J6.9 59.69,38.61 SW2.12 52.32,31.24 52.32,28.7 51.05,27.43 47.5,27.43 43.18,23.11 B5B4.1 43.18,20.84 43.19,20.83 43.19,18.74 42.23,17.78 BAT4.1
BAT5: length 102
  TOP w0.508: BAT5.1 51.18,17.78 52.96,16 61.47,16 62,15.47 J7.7 ; J6.12 62.23,51.82 60.71,53.34 R85.1
  BOTTOM w0.508: C43.2 49.99,10.39 49.99,13.77 48.26,15.49 BAT5.1 ; BAT5.1 46.69,17.78 45.72,18.75 B5B4.2 ; BAT5.1 49.85,17.78 50.8,18.73 B6B5.1 50.8,24.64 54.84,28.68 54.84,31.22 SW2.11 62.23,38.61 J6.11 J6.12 62.23,50.04 56.39,55.88 52.32,55.88 50.42,57.78 R64.1 R57.1 R47.1
BAT6: length 87.6
  TOP w0.508: R84.1 64.52,52.07 64.77,51.82 J6.14 ; v1(62,6.58) J7.8
  BOTTOM w0.508: v1(62,6.58) 60.45,8.13 58.42,8.13 57.38,9.17 C42.2 57.58,10.36 57.58,14.3 55.88,16 BAT6.1 ; BAT6.1 54.29,17.78 53.33,18.74 53.33,20.31 53.34,20.32 B6B5.2 ; BAT6.1 57.47,17.78 58.43,18.74 58.43,20.31 58.42,20.32 B7B6.1 58.42,26.42 59.94,27.94 59.94,33.78 SW2.10 64.77,38.61 J6.13 J6.14 64.77,49.78 57.53,57.02 R72.1 R53.1 R46.1
BAT7: length 80
  TOP w0.508: BAT7.1 J7.9 ; J6.16 67.31,53.82 68.01,54.52 R89.1
  BOTTOM w0.508: B7B6.2 60.96,19.3 60.95,19.3 60.95,18.74 61.91,17.78 BAT7.1 ; BAT7.1 65.09,17.78 66.05,18.74 66.05,20.31 66.04,20.32 B8B7.1 66.04,27.94 65.07,28.91 65.07,36.37 SW2.9 67.31,38.61 J6.15 J6.16 67.31,52.2 64.64,54.86 R63.1 R49.1 R44.1 ; BAT7.1 63.5,16.26 65.2,14.55 65.2,10.36 C41.2
BAT8: length 90.1
  TOP w0.508: R88.1 71.74,54.52 69.85,52.63 J6.18 ; v1(63.5,6.6) J7.10
  BOTTOM w0.508: v1(63.5,6.6) 65.02,8.13 72.11,8.13 72.62,8.64 C40.2 72.82,10.36 72.82,14.3 71.12,16 BAT8.1 ; B8B7.2 68.58,18.54 69.34,17.78 BAT8.1 ; BAT8.1 72.9,17.78 73.66,18.54 B9B8.1 73.66,24.13 72.85,24.94 72.85,36.35 SW1.16 69.85,39.34 J6.17 J6.18 69.85,53.59 68.81,54.64 68.81,58.27 R62.1 R45.1 R43.1
BAT9: length 97.2
  TOP w0.508: R90.1 72.39,50.97 J6.20 ; BAT9.1 75.18,17.78 73.41,19.56 69.09,19.56 65,15.47 J7.11
  BOTTOM w0.508: 78.77,17.78 78.74,17.75 78.74,16 80.44,14.3 80.44,10.36 C39.2 ; 78.77,17.78 79.89,17.78 81.03,18.91 B10B9.1 81.03,26.92 80.47,27.48 80.47,31.27 SW1.15 72.39,39.34 J6.19 J6.20 72.39,52.07 76.58,56.26 R71.1 R42.1 R41.1 ; 78.77,17.78 BAT9.1 77.15,17.78 76.19,18.74 76.19,22.09 B9B8.2
BAT10: length 114.5
  TOP w0.508: R95.1 78.91,54.52 74.93,50.55 J6.22 ; v1(65,6.07) J7.12
  BOTTOM w0.508: R37.1 R40.1 R60.1 83.69,56.26 82.8,55.37 78.99,55.37 74.93,51.31 J6.22 J6.21 74.93,39.34 SW1.14 83.03,31.24 83.03,27.97 B11B10.1 88.9,19.56 88.91,19.55 88.91,18.74 87.95,17.78 BAT10.1 ; BAT10.1 86.36,16 88.09,14.27 88.09,10.39 C38.2 87.86,8.61 87.12,7.87 74.68,7.87 73.91,7.11 65.79,7.11 65,6.33 v1(65,6.07) ; BAT10.1 84.77,17.78 83.57,18.99 B10B9.2
BAT11: length 126.4
  TOP w0.508: R94.1 82.72,54.52 77.47,49.28 J6.24 ; BAT11.1 90.81,17.78 89.03,16 67.31,16 66.5,15.19 J7.13
  BOTTOM w0.508: B11B10.2 91.44,19.05 92.71,17.78 BAT11.1 ; BAT11.1 93.98,16.26 95.68,14.55 95.68,10.36 C37.2 ; BAT11.1 95,17.78 96.27,19.05 B12B11.1 96.27,26.67 91.44,31.5 85.32,31.5 SW1.13 77.47,39.34 J6.23 J6.24 77.47,50.04 80.83,53.4 88.2,53.4 90.81,56.01 R59.1 R39.1 R33.1
BAT12: length 149.2
  TOP w0.508: R93.1 87.25,53.72 85.34,51.82 82.04,51.82 80.01,49.78 J6.26 ; v1(66.5,6.05) J7.14
  BOTTOM w0.508: BAT12.1 103.19,17.78 104.14,18.73 B13B12.1 104.14,23.88 95,33.02 86.33,33.02 SW1.12 80.01,39.34 J6.25 J6.26 80.01,50.04 82.04,52.07 93.98,52.07 97.92,56.01 R55.1 R38.1 R29.1 ; BAT12.1 100.01,17.78 99.05,18.74 99.05,18.8 98.81,19.05 B12B11.2 ; BAT12.1 101.6,16.26 103.3,14.55 103.3,10.36 C36.2 103.3,9.96 103.3,7.54 101.81,6.05 v1(66.5,6.05)
BAT13: length 160.9
  TOP w0.508: J7.15 68,14.22 68.51,14.73 103.5,14.73 106.55,17.78 BAT13.1 ; R92.1 91.19,53.59 87.88,50.29 83.31,50.29 82.55,49.53 J6.28
  BOTTOM w0.508: BAT13.1 109.22,16.26 110.92,14.55 110.92,10.36 C35.2 ; BAT13.1 110.81,17.78 111.51,18.48 B14B13.1 111.51,24.13 101.09,34.54 87.35,34.54 SW1.11 82.55,39.34 J6.27 J6.28 82.55,49.53 83.57,50.55 99.57,50.55 105.03,56.01 R58.1 R36.1 R25.1 ; BAT13.1 107.63,17.78 106.67,18.74 106.67,19.55 106.68,19.56 B13B12.2
BAT14: length 225.3
  TOP w0.508: J6.30 90.55,48.51 95,52.96 R91.1 95,54.58 95.99,54.58 96.52,55.12 96.52,86.36 R18.1
  TOP w0.635: J7.16 68,4.5 v1(68.54,5.04)
  BOTTOM w0.203: P+B14.1 119.34,22.06
  BOTTOM w0.508: R35.1 R21.1 R56.1 112.14,56.01 111.25,55.12 107.95,55.12 101.35,48.51 J6.30 J6.29 85.09,39.12 85.74,38.47 85.97,38.47 SW1.10 87.33,37.11 87.33,36.88 88.14,36.07 106.07,36.07 114.88,27.25 118.11,27.25 119.34,26.02 119.34,25.18 R187.2 119.34,24.75 119.34,22.06 ; P+B14.1 119.38,22.02 119.38,18.73 118.43,17.78 BAT14.1 ; BAT14.1 116.84,16.26 118.54,14.55 118.54,10.36 C34.2 118.34,9.59 113.79,5.04 v1(68.54,5.04) ; BAT14.1 115.25,17.78 114.05,18.99 B14B13.2
C0: length 90.1
  TOP w0.203: C61.2 42.65,60.57 42.65,58.65 41.91,57.91 R83.2 ; J2.14 44.23,114.14 47.24,111.12 58.98,111.12 60.23,109.87 U1.30
  TOP w0.254: 42.65,60.66 42.65,60.59 C61.2 ; 42.65,60.66 42.6,60.6 ; 42.65,60.66 42.65,61.75 31.24,73.15 31.24,107.82 37.56,114.14 J2.14
C1: length 89.6
  TOP w0.203: R82.2 45.47,58.17 46.46,59.16 C60.2 C61.1 ; J2.16 36.85,109.73 58.97,109.73 U1.32
  TOP w0.254: C61.1 44.2,60.62 44.2,62.74 33.78,73.15 33.78,108.31 J2.16
  BOTTOM w0.203: J2.16 33.74,112.83 C84.1
C2: length 80.2
  TOP w0.203: R81.2 49.28,57.66 50.27,58.65 C59.2 C60.1 48.03,60.58
  TOP w0.254: U1.34 58.14,104.39 39.38,104.39 J3.2 37.81,72.68 48.03,62.46 48.03,60.58
  BOTTOM w0.203: C33.1 35.51,100.53 J3.2
C3: length 75
  TOP w0.203: R87.2 53.09,57.66 54.08,58.65 C58.2 C59.1
  TOP w0.254: U1.36 57.98,102.82 44.99,102.82 J3.4 41.41,73.15 51.87,62.69 C59.1
  BOTTOM w0.203: J3.4 39.14,96.97 C32.1
C4: length 70
  TOP w0.203: 55.65,60.58 C58.1 C57.2 57.89,58.9 56.9,57.91 R86.2
  TOP w0.254: U1.38 57.92,101.35 50.7,101.35 J3.6 45,73.87 55.65,63.22 55.65,60.58
  BOTTOM w0.203: C31.1 43.57,94.12 43.57,94.22 J3.6
C5: length 64.8
  TOP w0.203: 59.46,60.58 C57.1 C56.2 61.7,58.65 60.71,57.66 R85.2
  TOP w0.254: U1.40 57.56,99.57 56.11,99.57 J3.8 48.59,74.35 59.44,63.5 59.44,60.6 59.46,60.58
  BOTTOM w0.203: J3.8 46.17,89.63 C30.1
C6: length 62.2
  TOP w0.203: 63.27,60.58 C56.1 C55.2 65.51,58.9 64.52,57.91 R84.2
  TOP w0.254: 63.27,60.58 63.27,62.97 52.18,74.06 J3.10 59.44,95.71 59.44,100.03 62.72,103.32
  BOTTOM w0.203: J3.10 50.65,86.92 50.6,86.92 C29.1
C7: length 60.5
  TOP w0.203: 67.08,60.58 C55.1 C54.2 69.32,58.65 68.33,57.66 R89.2
  TOP w0.254: 67.08,60.58 67.08,63.47 55.77,74.78 J3.12 60.96,90.05 60.96,100.14 63.43,102.61 U1.44
  BOTTOM w0.203: C28.1 54.03,82.99 54.03,83.13 J3.12
C8: length 58
  TOP w0.203: 70.89,60.58 C54.1 C53.2 73.13,58.65 72.14,57.66 R88.2
  TOP w0.254: 70.89,60.58 70.89,64.74 59.37,76.27 J3.14 62.4,84.3 62.4,100.16 U1.46
  BOTTOM w0.203: J3.14 58.06,79.97 58.06,79.91 C27.1
C9: length 56.2
  TOP w0.203: C53.1 74.7,60.58 74.81,60.68 74.91,60.58 C52.2 76.94,60.58 76.94,58.65 75.95,57.66 R90.2
  TOP w0.254: 74.81,60.68 74.68,60.82 74.68,65.96 J3.16 64.03,78.76 64.03,100.39 U1.48
  BOTTOM w0.203: J3.16 61.63,76.35 61.62,76.35 C26.1
C10: length 55.7
  TOP w0.203: R95.2 79.76,57.91 80.75,58.9 80.75,60.58 C51.2
  TOP w0.254: U1.50 69.09,100.32 69.09,81.11 J4.2 78.51,71.69 C52.1 C51.2
  BOTTOM w0.203: C25.1 70.71,79.41 J4.2
C11: length 57.7
  TOP w0.203: C50.2 84.56,60.58 84.56,58.39 83.44,57.28 R94.2
  TOP w0.254: C50.2 C51.1 82.32,75.06 J4.4 70.61,86.77 70.61,100.21 U1.52
  BOTTOM w0.203: C24.1 74.3,82.93 J4.4
C12: length 59.7
  TOP w0.203: C50.1 C49.2 88.37,60.58 88.37,58.65 87.25,57.53 R93.2
  TOP w0.254: U1.54 72.64,99.59 72.64,91.92 77.89,86.68 J4.6 86.13,78.44 C50.1
  BOTTOM w0.203: J4.6 77.89,86.45 C23.1
C13: length 62.3
  TOP w0.203: R92.2 91.19,57.15 92.18,58.14 C48.2 C49.1
  TOP w0.254: C49.1 89.94,81.81 J4.8 78.03,93.73 76.96,93.73 74.17,96.52 74.17,99.48 U1.56
  BOTTOM w0.203: J4.8 81.48,89.97 C22.1
C14: length 70.3
  TOP w0.203: 93.78,58.62 93.75,58.65 93.75,60.58 ; 93.78,58.62 C48.1 ; 93.78,58.62 95,57.4 R91.2
  TOP w0.254: 93.75,60.58 93.75,82.14 90.42,85.47 90.42,88.51 J4.10 ; 70.69,104.38 70.67,104.38 69.87,105.18 v1(69.37,105.18)
  L3_GND w0.203: 69.43,105.12 v1(69.37,105.18) ; J4.10 78.48,93.86 69.43,102.91
  L3_GND w0.254: 69.43,102.91 69.43,105.12
  BOTTOM w0.203: C20.1 85.21,93.86 J4.10
CPN: length 30
  TOP w0.203: v1(75.35,102.1) 74.64,102.81 C1.1 74.17,103.26 74.17,103.71 72.1,105.78 U1.62 ; J4.14 94.63,98.68 94.63,98.63 96.28,96.97 96.28,96.88 97.54,95.63 CPN.1
  L3_GND w0.203: v1(75.35,102.1) 91.2,102.1 J4.14
CPP: length 28.4
  TOP w0.203: J4.15 95.9,101 95.9,100.95 96.52,100.33 CPP.1 ; v1(76.46,103.22) 75.75,103.93 C1.2 75.75,103.96 74.96,104.75 73.84,104.75 72.46,106.13 U1.63
  L3_GND w0.203: v1(76.46,103.22) 77.03,103.22 77.24,103.43 77.7,103.43 77.91,103.22 93.68,103.22 J4.15
CS0: length 16.2
  TOP w0.254: U2.3 119.24,49.9 117.09,47.75 117.09,45.85 MINIQ1.9
  BOTTOM w0.254: D13.1 MINIQ1.9
CS0_HV: length 86.2
  TOP w0.254: v1(119.18,65.53) 119.24,65.47 U2.12
  L3_GND w0.178: v1(74.14,121.67) 74.14,120.3 86.69,107.75 99.26,107.75 109.35,97.66 109.35,91.69 117.22,83.82 117.22,67.49 v1(119.18,65.53)
  BOTTOM w0.254: R1.1 73.98,121.83 v1(74.14,121.67)
CS1: length 2.6
  BOTTOM w0.203: D19.1 MINIQ1.14
CS2: length 2.6
  BOTTOM w0.203: D18.1 MINIQ1.16
DCIN: length 41.8
  TOP w0.254: 72.97,103.96 72.97,104.21 U1.61
  TOP w0.381: 77.74,96.88 C6.1 77.85,95.32 ; 75.68,100.71 C18.1 76.08,98.66
  TOP w0.635: 79.63,94.99 C6.1 ; 79.63,94.99 79.65,94.97 ; 79.63,94.99 79.63,94.97 79.65,94.97 ; 79.65,94.97 81.16,94.97 81.43,95.25 ; 81.43,95.25 81.71,94.97 83.16,94.97 87.44,99.25 J4.13 97.89,91.82 ; 81.43,95.25 D40.A ; 97.89,91.82 100.2,91.82 100.33,91.69 R17.2 ; 97.89,91.82 DCIN.1
  BOTTOM w0.762: C19.1 89.27,100.47 89.27,100.45 J4.13
GPIO0/AUXIN0: length 44.7
  TOP w0.203: 60.88,118.44 60.55,118.11 60.2,118.11 58.7,119.61 58.7,127.39 J2.5 53.81,132.27 R148.2 ; 60.88,118.44 61.47,117.86 61.47,115 63.41,113.05 U1.21 ; 60.88,118.44 C8.1
  BOTTOM w0.203: J2.5 55.24,130.84 R116.2 55.88,132.44 58.93,135.48 J5.4
GPIO0/AUXIN0_OUT: length 56.4
  TOP w0.203: D5.1 79.76,162.18 ; 79.76,162.18 79.76,162.18 80.52,162.18 81.53,163.19 82.72,163.19 C106.1 ; 79.76,162.18 79.76,163.65 79.39,164.02 GPIO_AUX0.1 ; 79.76,162.18 79.12,162.18 78.49,162.81 78.49,163.8 78.03,164.26 THERM1.1 75.62,164.26 75.18,163.83 75.18,160.91 GP/AUX0.1
  BOTTOM w0.203: R116.1 56.03,134.14 57.75,135.85 57.75,149.95 J5.3 58.93,152.78 61.59,155.45 69.6,155.45 72.9,158.75 73.03,158.75 GP/AUX0.1
GPIO1/AUXIN1: length 45.9
  TOP w0.203: R143.1 52.29,130.21 J2.6 57.02,125.47 57.02,119.39 59.26,117.16 59.6,117.16 59.87,117.42 ; 59.87,117.42 60.45,116.84 60.45,115.31 63.06,112.7 U1.22 ; 59.87,117.42 C9.1
  BOTTOM w0.203: J2.6 52.7,129.79 R117.2 53.19,132.56 53.59,132.97 53.59,144.15 56.39,146.94 J5.6
GPIO1/AUXIN1_OUT: length 48.5
  TOP w0.203: GPIO_AUX1.1 69.02,164.07 69.34,163.75 69.34,162.09 ; 69.34,162.09 69.43,162.18 69.98,162.18 71.12,163.32 C107.1 ; 69.34,162.09 D6.1 69.24,162.18 68.99,162.18 68.2,162.97 68.2,164.04 67.93,164.31 THERM2.1 65.2,164.31 64.9,164.01 64.9,160.66 GP/AUX1.1
  BOTTOM w0.203: R117.1 52.7,144.91 55.12,147.32 55.12,150.37 55.88,151.13 J5.5 56.39,152.27 62.74,158.62 62.87,158.62 GP/AUX1.1
GPIO2/AUXIN2: length 43
  TOP w0.203: U1.23 62.71,112.34 59.44,115.61 59.44,115.82 58.85,116.41 ; J2.7 55.37,123.53 55.37,118.87 58.1,116.14 58.58,116.14 58.85,116.41 ; 58.85,116.41 C10.1
  BOTTOM w0.203: J2.7 50.29,128.61 R121.2 50.77,132.56 51.31,133.1 J5.10
GPIO2/AUXIN2_OUT: length 45.5
  TOP w0.203: C108.1 61.34,163.32 60.2,162.18 59.28,162.18 D7.1 ; GP/AUX2.1 54.74,160.32 54.74,164.01 55.04,164.31 THERM3.1 57.61,164.31 57.91,164.01 57.91,162.69 58.42,162.18 59.08,162.18 D7.1 ; D7.1 59.18,164.08 58.81,164.45 GPIO_AUX2.1
  BOTTOM w0.203: R121.1 50.29,135.28 50.04,135.53 50.04,150.11 51.05,151.13 J5.9 51.31,156.84 52.96,158.5 GP/AUX2.1
GPIO3/AUXIN3: length 112.1
  TOP w0.203: J2.8 53.34,121.97 53.34,118.87 57.15,115.06 57.5,115.06 57.84,115.39 ; R137.1 94.19,161.16 92.3,161.16 91.99,161.48 C16.1 ; U1.24 62.35,111.99 60.17,114.17 59.05,114.17 57.84,115.39 ; 57.84,115.39 C11.1
  TOP w0.254: v1(74.04,138.05) 81.28,145.29 81.28,147.07 94.23,160.02
  TOP w0.305: 94.23,160.02 R137.1
  BOTTOM w0.203: v1(74.04,138.05) 74.04,133.6 69.72,129.29 67.31,129.29 62.94,124.92 J2.8 47.5,127.81 R118.2 47.98,132.56 48.34,132.92 48.34,139.65 48.77,140.08 J5.12
GPIO3/AUXIN3_OUT: length 45.4
  TOP w0.203: C105.1 50.93,163.19 49.81,162.08 D8.1 ; D8.1 48.48,162.08 47.88,162.69 47.88,163.78 47.4,164.26 THERM4.1 44.86,164.26 44.45,163.86 44.45,159.44 GP/AUX3.1 ; D8.1 49.02,163.83 48.63,164.22 GPIO_AUX3.1
  BOTTOM w0.203: R118.1 47.5,149.86 J5.11 48.83,151.19 48.83,155.05 GP/AUX3.1
GPIO4/AUXIN4: length 49.7
  TOP w0.203: 56.82,114.38 56.46,114.01 56.17,114.01 54.74,115.44 52.68,115.44 50.53,117.6 49.79,117.6 C86.1 48.77,118.62 48.77,119.36 J2.10 ; 56.82,114.38 57.78,113.41 59.53,113.41 U1.26 ; 56.82,114.38 C12.1
  BOTTOM w0.203: J2.10 42.42,125.71 R119.2 42.9,132.82 43.69,133.6 J5.16
GPIO4/AUXIN4_OUT: length 44.3
  TOP w0.203: CURRENTSENSE.2 29.96,165.01 30.38,164.59 33.55,164.59 THERM5.1 34.57,163.58 36.13,163.58 R185.2 36.45,163.27 36.46,163.26 36.46,161.5 D4.1
  BOTTOM w0.203: THERM5.1 39.12,159.03 39.12,157.86 43.69,153.29 J5.15 42.42,149.86 R119.1
GPIO5/AUXIN5: length 55.5
  TOP w0.203: 45.69,118.9 45.69,118.84 46.91,117.62 47.5,117.62 48.82,116.31 48.82,115.72 50.11,114.43 53.72,114.43 55.12,113.03 55.47,113.03 55.8,113.36 ; 55.8,113.36 56.26,112.9 59.33,112.9 U1.27 ; 55.8,113.36 C13.1
  TOP w0.635: 45.69,118.9 45.06,119.53 J2.11 43.1,121.43 R30.2
  BOTTOM w0.203: J5.18 40.51,147.96 40.51,140.46 40.79,140.18 40.79,133.12 40.49,132.82 R120.2 40.01,125.6 41.78,123.83 41.78,122.75 J2.11
GPIO5/AUXIN5_OUT: length 49.9
  TOP w0.203: 19.96,163.48 19.87,163.48 19.77,163.58 ; 19.96,163.48 R186.2 ; 19.96,163.48 D3.1 24.67,163.48 THERM6.1 25.11,163.49 R31.1 28.13,163.49 28.46,163.82 CURRENTSENSE.1
  BOTTOM w0.203: THERM6.1 26.67,163.7 29.46,160.91 31.37,160.91 J5.17 39.85,149.83 39.85,134.67 R120.1
GPIO8: length 2.4
  BOTTOM w0.203: D15.1 MINIQ1.5
HV: length 30.7
  TOP w0.203: HV.1 103.25,98.89 102.87,98.51 R23.2
  TOP w0.254: 85.84,104.64 J4.16 98,102.49 100.71,102.49 HV.1
  TOP w0.381: 95,105.49 J4.16 95.42,105.92
  TOP w0.508: 83.26,101.04 R19.2 82.51,100.47 81.97,101.02
  TOP w0.635: D40.C 83.84,97.65 83.84,99.14 82.69,100.29 R19.2
INT2: length 2.4
  BOTTOM w0.203: D16.1 MINIQ1.3
MINIQ_SHDNL: length 80.1
  BOTTOM w0.203: 118.36,50.29 D20.1 MINIQ1.12
  BOTTOM w0.254: SHDNL_SEL.1 101.1,109.74 104.67,106.17 111.53,106.17 117.6,100.1 117.6,98.17 117.12,97.69 117.12,95.4 117.11,95.38 117.11,82.31 123.19,76.23 123.19,57.02 119.38,53.21 119.38,51.31 118.36,50.29
PACK+: length 148
  TOP w0.508: 121.98,22.05 P+B14.2
  TOP w0.635: J7.17 69.5,12.6 70.1,13.21 76.45,13.21 77.34,12.32 112.75,12.32 114.17,10.9 118.24,10.9 118.87,11.53 118.87,13.03 C100.1 120.7,13.26 PACK+.1 123.19,20.84 121.98,22.05 ; P+B14.2 121.92,22.07 121.92,28.19 117.35,32.77 105.41,32.77 100.33,37.85 R17.1
  BOTTOM w0.508: P+B14.2 122.76,22.91 122.76,24.77 R187.1
RXLN: length 76.1
  TOP w0.203: U1.18 63.68,114.92 63.68,118.69 63.25,119.13 62.23,119.13 C80.1 62.12,119.68 62.12,120.25 61.09,121.28 61.09,121.29 60.68,121.69 60.68,132.18 62.99,134.49 62.99,135.41 62.71,135.69 J2.2 61.17,137.14 57.24,141.07 44.2,141.07 30.35,127.23 27.66,127.23 27.1,126.67 27.1,124.11 R138.2 RXLN.1
RXLP: length 76
  TOP w0.203: U1.17 64.08,115.22 64.08,118.86 63.5,119.45 63.5,120.4 C83.1 63,120.56 62.39,120.56 61.09,121.86 61.09,132.01 63.4,134.32 63.4,135.58 62.97,136.01 J2.1 61.39,137.49 57.4,141.48 44.03,141.48 30.18,127.64 27.69,127.64 27.1,128.22 27.1,130.39 R140.2 29.97,130.81 RXLP.1
RXN1: length 7.4
  TOP w0.203: RXLP_CONN.1 7.89,126.71 8.19,127 10.19,127 10.99,126.2 C89.1 10.99,125.98 10.67,125.67 RXN1.1
RXN2: length 7.1
  TOP w0.203: RXUP_CONN.2 116.98,145.05 116.2,144.27 116.54,144.27 118.36,142.44 RXN2.1
RXP1: length 7.3
  TOP w0.203: RXP1.1 10.67,129.1 C90.1 10.1,127.89 8.21,127.89 7.9,128.21 7.89,128.21 RXLP_CONN.2
RXP2: length 7.1
  TOP w0.203: RXP2.1 118.36,149.17 116.51,147.32 116.2,147.32 116.99,146.54 119.14,146.54 RXUP_CONN.1
RXUN: length 54.8
  TOP w0.203: RXUN.1 95.22,143.75 R129.2 95.74,144.67 94.77,145.64 89.83,145.64 76.08,131.89 J1.12 ; J1.12 74.55,130.32 73.58,129.35 73.58,117.46 70.49,114.37 70.24,114.38 69.72,113.85 U1.12 ; J1.12 77.8,132.05 C77.1
RXUP: length 54.9
  TOP w0.203: 74.33,132.12 75.73,132.12 89.66,146.05 94.87,146.05 95.74,146.92 R130.2 95.22,147.84 RXUP.1 ; U1.13 69.57,114.4 69.97,114.81 70.22,114.8 73.17,117.76 73.17,129.52 74.28,130.63 J1.13 75.97,133.81 C81.1
  TOP w0.254: J1.13 74.33,132.12
SCLK: length 15.5
  TOP w0.254: U2.4 119.89,48.9 119.7,48.71 119.7,45.91 MINIQ1.11
  BOTTOM w0.254: D12.1 MINIQ1.11
SCLK_HV: length 80.5
  TOP w0.254: U2.11 v1(119.89,64.9)
  L3_GND w0.178: v1(119.89,64.9) 119.89,65.72 117.73,67.88 117.73,83.95 117.68,84 117.68,84.01 112.01,89.67 112.01,96.14 99.9,108.25 87.03,108.25 v1(78.71,116.56)
  BOTTOM w0.254: R3.1 78.07,116.56 v1(78.71,116.56)
SDI: length 17
  TOP w0.254: U2.2 118.59,53.95 116.71,52.07 116.71,49.91 114.62,47.82 114.62,45.91 MINIQ1.7
  BOTTOM w0.254: D14.1 MINIQ1.7
SDI_HV: length 101.2
  TOP w0.254: 118.59,62.99 118.59,64.73 118.59,64.73 ; 118.59,62.99 118.59,63 118.59,64.73 ; 118.59,62.99 U2.13 ; v1(62.89,130.79) 62.89,131.07 62.35,131.61 R2.1 ; 118.59,64.73 v1(118.65,64.8)
  L3_GND w0.178: v1(118.65,64.8) 118.65,64.8 116.59,66.87 116.59,83.69 106.93,93.34 106.93,98.81 98.45,107.29 86,107.29 62.89,130.41 v1(62.89,130.79)
SDO: length 16
  TOP w0.254: U2.5 120.54,53.07 122.11,51.5 122.11,45.78 MINIQ1.13
  BOTTOM w0.254: D11.1 MINIQ1.13
SDO_HV: length 96.6
  TOP w0.203: v1(67.82,126.87) 67.69,126.75 67.34,126.75 67.06,127.03 66.97,127.03 R4.1
  TOP w0.254: U2.10 v1(120.54,65.53)
  L3_GND w0.178: v1(67.82,126.87) 67.94,126.75 69.98,126.75 88.02,108.71 101.07,108.71 109.25,100.52 109.5,100.52 109.82,100.2 109.82,99.95 114.55,95.22 114.55,88.01 118.24,84.33 118.24,69.03 120.54,66.72 v1(120.54,65.53)
SHDNL: length 29.8
  TOP w0.254: SHDNL.1 101.73,114.05 SHDNL_SEL.2 99.19,111.51 96.77,111.51 J1.1
  BOTTOM w0.254: J1.1 77.17,110.57 R22.2
SW0: length 94
  TOP w0.203: 58.17,110.36 59.03,110.36 59.88,109.52 U1.31
  TOP w0.508: J2.15 43.61,112.35 45.59,110.36 58.17,110.36
  BOTTOM w0.508: R74.2 R54.2 R77.2 12.67,66.7 12.67,85.7 34.42,107.44 36.99,107.44 39.82,110.28 C75.2 37.82,112.31 J2.15 36.83,113.34 36.83,113.79 C85.1
SW1: length 85.2
  TOP w0.254: U1.33 58.2,105.16 57.4,105.16
  TOP w0.508: 57.4,105.16 36.55,105.16 J3.1
  BOTTOM w0.508: C75.1 40.13,108.36 40.13,106.65 40.1,106.65 C74.2 38.07,104.62 J3.1 19.53,88.14 19.53,66.7 19.68,66.55 19.68,58.42
SW2: length 79.1
  TOP w0.254: 57.66,103.63 58.09,103.63 U1.35
  TOP w0.508: 57.66,103.63 42.21,103.63 J3.3
  BOTTOM w0.508: J3.3 26.39,87.81 26.39,66.7 R51.2 R69.2 R68.2 ; J3.3 39.61,103.9 C74.1 ; J3.3 42.13,101.03 42.64,101.53 42.64,101.57 C73.2
SW3: length 72.5
  TOP w0.254: U1.37 57.98,102.11 57.4,102.11
  TOP w0.508: J3.5 47.87,102.11 57.4,102.11
  BOTTOM w0.508: C73.1 43.2,99.87 J3.5 ; C72.2 46.57,97.89 46.57,97.85 46.26,97.54 43.3,97.54 J3.5 ; J3.5 33.25,87.49 33.25,66.7 R50.2 R65.2 R67.2
SW4: length 65.8
  TOP w0.254: 57.15,100.58 57.87,100.58 U1.39
  TOP w0.508: J3.7 53.53,100.58 57.15,100.58
  BOTTOM w0.508: J3.7 40.36,87.41 40.36,66.7 R48.2 R61.2 R66.2 ; J3.7 46.79,95.84 C72.1 ; J3.7 46.91,93.73 50.07,93.73 50.07,93.76 C71.2
SW5: length 62.6
  TOP w0.254: U1.41 58.67,99.98 58.67,98.81
  TOP w0.508: 58.67,98.81 58.67,98.54 J3.9
  BOTTOM w0.508: J3.9 50.39,91.82 C71.1 ; J3.9 44.2,84.06 44.2,72.39 47.62,68.96 R47.2 R57.2 R64.2 ; J3.9 54.22,90.25 54.7,90.74 C70.2
SW6: length 61.6
  TOP w0.254: U1.43 60.2,100.09 60.2,98.81
  TOP w0.508: J3.11 60.2,92.88 60.2,98.81
  BOTTOM w0.508: J3.11 47.88,80.56 47.88,75.06 54.74,68.2 R46.2 R53.2 R72.2 ; J3.11 53.98,87.79 55.79,89.6 ; J3.11 56.97,86.66 57.33,87.02 57.33,87.05 C69.2
SW7: length 61.8
  TOP w0.254: 61.72,99.31 61.72,100.2 U1.45
  TOP w0.508: J3.13 61.72,87.22 61.72,99.31
  BOTTOM w0.508: C68.2 60.62,83.11 60.62,83.07 J3.13 ; J3.13 57.57,85.03 C69.1 ; J3.13 51.82,77.32 51.82,76.45 58.42,69.85 59.57,69.85 61.85,67.57 61.85,58.42
SW8: length 55.9
  TOP w0.254: 63.25,99.57 63.25,100.31 U1.47
  TOP w0.508: 63.25,99.57 63.25,81.56 J3.15
  BOTTOM w0.508: 62.52,82.74 61.16,81.38 J3.15 64.7,79.48 C67.2 65.28,79.96 65.28,75.18 71.75,68.71 R43.2 R45.2 R62.2
SW9: length 56.4
  TOP w0.254: 68.33,99.82 68.33,100.37 U1.49
  TOP w0.508: J4.1 68.07,78.54 68.07,99.57 68.33,99.82
  BOTTOM w0.508: C67.1 66.83,79.78 J4.1 ; J4.1 74.98,71.63 76.45,71.63 79.38,68.71 R41.2 R42.2 R71.2 ; J4.1 68.91,81.61 C66.2
SW10: length 58.7
  TOP w0.254: U1.51 69.85,100.26 69.85,99.82
  TOP w0.508: J4.3 69.85,83.94 69.85,99.82
  BOTTOM w0.508: J4.3 72.5,80.91 78.74,74.68 80.29,74.68 86.49,68.48 R37.2 R40.2 R60.2 ; J4.3 72.22,81.29 C66.1 ; J4.3 72.5,85.1 C65.2
SW11: length 61.8
  TOP w0.254: U1.53 71.63,99.9 71.63,99.17
  TOP w0.508: 71.63,99.17 71.63,89.35 J4.5
  BOTTOM w0.508: C65.1 74.98,84.88 J4.5 ; J4.5 85.29,75.69 86.39,75.69 93.6,68.48 R33.2 R39.2 R59.2 ; J4.5 76.09,87.89 C64.2
SW12: length 65.5
  TOP w0.203: 73.41,99.54 73.41,99.24
  TOP w0.254: 69.63,103.32 73.41,99.54
  TOP w0.508: 73.41,99.24 73.41,94.76 J4.7
  BOTTOM w0.508: R55.2 R38.2 R29.2 100.71,68.48 93.75,75.44 92.2,75.44 80.64,87 80.64,87.52 J4.7 ; C64.1 78.69,89.47 J4.7 ; J4.7 79.69,90.9 C63.2
SW13: length 74.4
  TOP w0.254: U1.57 70.32,104.02 70.32,104.02 69.75,104.59 68.74,104.59 v1(68.71,104.57)
  L3_GND w0.508: J4.9 78.75,92.07 68.71,102.11 v1(68.71,104.57)
  BOTTOM w0.508: J4.9 83.28,94.42 C62.2 ; J4.9 80.75,92.07 80.57,92.25 80.57,92.29 C63.1 ; J4.9 99.91,75.44 100.87,75.44 107.82,68.48 R25.2 R36.2 R58.2
SW14: length 69.7
  TOP w0.254: U1.59 71.03,104.73 72.14,103.62
  TOP w0.381: 72.14,103.62 v1(72.14,103.12)
  BOTTOM w0.508: v1(72.14,103.12) 78.79,96.47 83.5,96.47 C62.1 83.79,96.49 86.04,96.49 J4.11 107.35,75.18 108.66,75.18 114.94,68.91 R35.2 R21.2 R56.2
